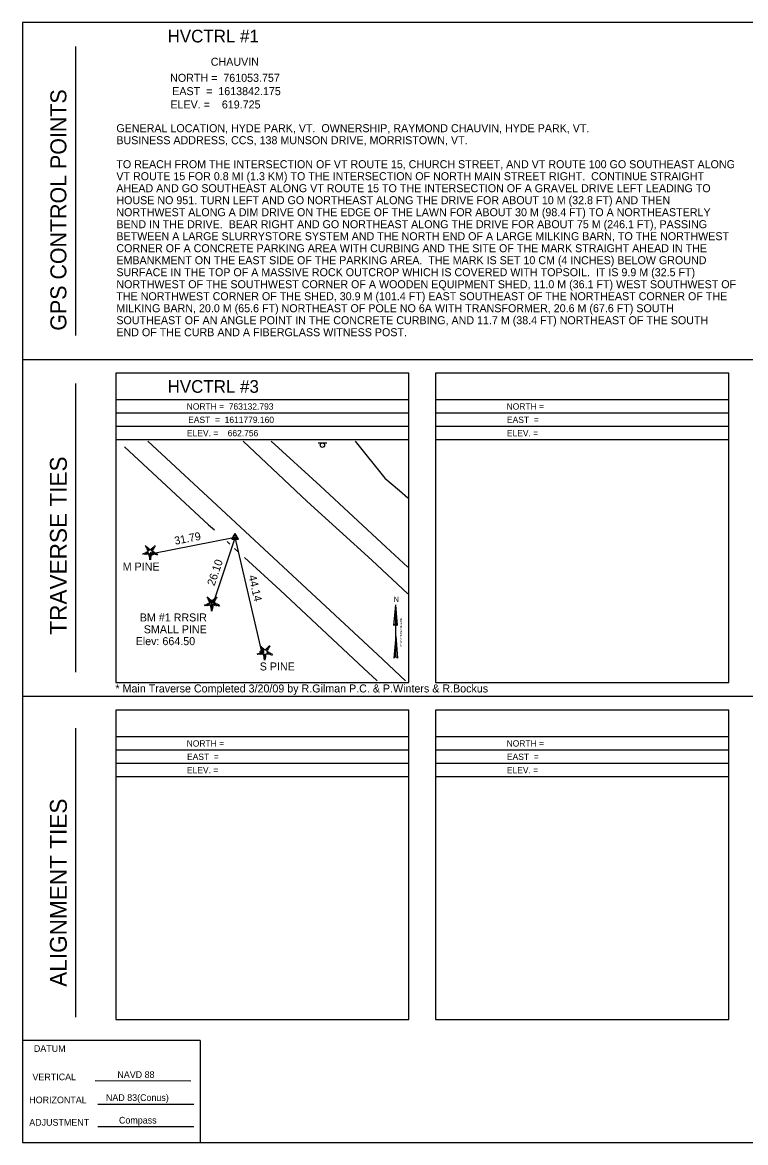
# Model space of a CAD drawing. Extents: x 1610875 to 1611515, y 762695 to 763115.
# Drawn here: x 1610874.6 to 1611145.9, y 762695 to 763115 of the extents above; entities that cross this region are included whole.
import ezdxf

# ---------------------------------------------------------------- set-up
doc = ezdxf.new("R2010")
doc.units = 0
for name, color, linetype in [('C_C', 7, 'Continuous'), ('CBP', 7, 'Continuous'), ('CPBM', 7, 'Continuous'), ('CPSM', 7, 'Continuous'), ('Default', 7, 'Continuous'), ('L_C', 7, 'Continuous'), ('LAWA', 7, 'Continuous'), ('LTC', 7, 'Continuous'), ('NBL2', 7, 'Continuous'), ('NNA_P', 7, 'Continuous'), ('PET', 7, 'Continuous'), ('PSP', 7, 'Continuous'), ('SSGN', 7, 'Continuous')]:
    doc.layers.add(name, color=color, linetype=linetype)

msp = doc.modelspace()

# ---------------------------------------------------------------- linework, layer by layer
at = {"layer": 'CBP'}
for centre, radius in [((1610923.26, 762915.95), 0.625), ((1610923.26, 762915.95), 0.0833), ((1610946.1, 762897.28), 0.625), ((1610946.1, 762897.28), 0.0833), ((1610964.42, 762878.99), 0.625), ((1610964.42, 762878.99), 0.0833)]:
    msp.add_circle(centre, radius, dxfattribs=at)
at = {"layer": 'CPBM'}
for p, q in [((1610945.07, 762897.36), (1610945.07, 762898.36)), ((1610945.07, 762898.36), (1610946.07, 762898.36)), ((1610946.07, 762897.36), (1610945.07, 762897.36)), ((1610945.58, 762897.87), (1610945.58, 762897.87)), ((1610945.58, 762897.87), (1610945.58, 762897.87)), ((1610946.07, 762898.36), (1610946.07, 762897.36))]:
    msp.add_line(p, q, dxfattribs=at)
at = {"layer": 'CPSM'}
for p, q in [((1610953.22, 762921.28), (1610954.47, 762923.44)), ((1610953.22, 762921.28), (1610954.47, 762922)), ((1610955.72, 762921.28), (1610954.47, 762923.44)), ((1610954.47, 762922), (1610954.47, 762923.44)), ((1610954.47, 762922), (1610954.47, 762922)), ((1610954.47, 762922), (1610955.72, 762921.28)), ((1610953.22, 762921.28), (1610955.72, 762921.28))]:
    msp.add_line(p, q, dxfattribs=at)
at = {"layer": 'Default'}
for p, q in [((1610923.26, 762915.95), (1610954.47, 762922)), ((1610954.47, 762922), (1610946.1, 762897.28)), ((1610964.42, 762878.99), (1610954.47, 762922))]:
    msp.add_line(p, q, dxfattribs=at)
at = {"layer": 'LAWA'}
msp.add_lwpolyline([(1610999.4, 762958.05), (1611010.54, 762944.1), (1611016.04, 762939.57), (1611019.14, 762936.77)], dxfattribs=at)
at = {"layer": 'LTC'}
for p, q in [((1610920.68, 762918.66), (1610921.03, 762918.92)), ((1610920.89, 762918.2), (1610921.42, 762918.58)), ((1610921.1, 762917.73), (1610921.8, 762918.24)), ((1610921.31, 762917.27), (1610922.18, 762917.91)), ((1610921.53, 762916.81), (1610922.54, 762917.55)), ((1610922.54, 762917.55), (1610923.54, 762916.82)), ((1610922.96, 762917.86), (1610923.77, 762917.27)), ((1610923.33, 762918.21), (1610924.01, 762917.71)), ((1610923.7, 762918.56), (1610924.25, 762918.16)), ((1610924.08, 762918.91), (1610924.49, 762918.6)), ((1610919.71, 762915.94), (1610919.86, 762915.48)), ((1610920.16, 762916.16), (1610920.38, 762915.51)), ((1610920.62, 762916.38), (1610920.89, 762915.54)), ((1610921.08, 762916.59), (1610921.41, 762915.57)), ((1610921.53, 762916.81), (1610921.92, 762915.62)), ((1610923.15, 762915.62), (1610921.92, 762915.62)), ((1610923.11, 762915.12), (1610921.96, 762915.12)), ((1610923.03, 762914.62), (1610922.04, 762914.62)), ((1610922.94, 762914.12), (1610922.11, 762914.12)), ((1610922.86, 762913.62), (1610922.18, 762913.62)), ((1610923.54, 762916.82), (1610923.15, 762915.62)), ((1610923.98, 762916.55), (1610923.64, 762915.51)), ((1610924.42, 762916.3), (1610924.13, 762915.42)), ((1610924.87, 762916.05), (1610924.63, 762915.32)), ((1610925.31, 762915.8), (1610925.12, 762915.23)), ((1610942.83, 762896.73), (1610942.98, 762896.26)), ((1610943.28, 762896.95), (1610943.49, 762896.3)), ((1610943.74, 762897.17), (1610944.01, 762896.33)), ((1610943.79, 762899.45), (1610944.15, 762899.71)), ((1610944, 762898.99), (1610944.53, 762899.37)), ((1610944.19, 762897.38), (1610944.52, 762896.36)), ((1610944.21, 762898.52), (1610944.92, 762899.03)), ((1610944.42, 762898.06), (1610945.3, 762898.69)), ((1610944.65, 762897.6), (1610945.66, 762898.34)), ((1610944.65, 762897.6), (1610945.03, 762896.41)), ((1610946.26, 762896.41), (1610945.03, 762896.41)), ((1610945.66, 762898.34), (1610946.65, 762897.61)), ((1610946.08, 762898.65), (1610946.89, 762898.06)), ((1610946.65, 762897.61), (1610946.26, 762896.41)), ((1610946.45, 762899), (1610947.13, 762898.5)), ((1610947.09, 762897.34), (1610946.75, 762896.3)), ((1610946.82, 762899.34), (1610947.37, 762898.95)), ((1610947.19, 762899.69), (1610947.61, 762899.39)), ((1610947.54, 762897.09), (1610947.25, 762896.2)), ((1610947.98, 762896.84), (1610947.74, 762896.11)), ((1610948.43, 762896.59), (1610948.24, 762896.01)), ((1610946.23, 762895.91), (1610945.08, 762895.91)), ((1610946.14, 762895.41), (1610945.15, 762895.41)), ((1610946.06, 762894.91), (1610945.23, 762894.91)), ((1610945.97, 762894.41), (1610945.3, 762894.41)), ((1610963.66, 762881.12), (1610964.02, 762881.38)), ((1610963.87, 762880.66), (1610964.4, 762881.04)), ((1610964.08, 762880.19), (1610964.79, 762880.7)), ((1610964.29, 762879.73), (1610965.17, 762880.36)), ((1610964.52, 762879.27), (1610965.53, 762880.01)), ((1610965.53, 762880.01), (1610966.53, 762879.28)), ((1610965.95, 762880.32), (1610966.76, 762879.73)), ((1610966.32, 762880.67), (1610967, 762880.17)), ((1610966.69, 762881.02), (1610967.24, 762880.62)), ((1610967.06, 762881.36), (1610967.48, 762881.06)), ((1610962.7, 762878.4), (1610962.85, 762877.94)), ((1610963.15, 762878.62), (1610963.36, 762877.97)), ((1610963.61, 762878.84), (1610963.88, 762878)), ((1610964.06, 762879.05), (1610964.39, 762878.03)), ((1610964.52, 762879.27), (1610964.9, 762878.08)), ((1610966.14, 762878.08), (1610964.9, 762878.08)), ((1610966.1, 762877.58), (1610964.95, 762877.58)), ((1610966.01, 762877.08), (1610965.02, 762877.08)), ((1610965.93, 762876.58), (1610965.1, 762876.58)), ((1610965.85, 762876.08), (1610965.17, 762876.08)), ((1610966.53, 762879.28), (1610966.14, 762878.08)), ((1610966.96, 762879.01), (1610966.63, 762877.97)), ((1610967.41, 762878.76), (1610967.12, 762877.88)), ((1610967.85, 762878.51), (1610967.62, 762877.78)), ((1610968.3, 762878.26), (1610968.11, 762877.69))]:
    msp.add_line(p, q, dxfattribs=at)
at = {"layer": 'NBL2'}
for p, q in [((1610894.6, 762997.69), (1610894.6, 763106.03)), ((1610874.6, 762988.69), (1611514.6, 762988.69)), ((1610894.6, 762871.36), (1610894.6, 762979.69)), ((1611019.6, 762973.53), (1610909.6, 762973.53)), ((1611139.6, 762973.53), (1611029.6, 762973.53)), ((1611019.6, 762968.53), (1610909.6, 762968.53)), ((1611139.6, 762968.53), (1611029.6, 762968.53)), ((1611019.6, 762963.53), (1610909.6, 762963.53)), ((1611139.6, 762963.53), (1611029.6, 762963.53)), ((1611019.6, 762958.53), (1610909.6, 762958.53)), ((1611139.6, 762958.53), (1611029.6, 762958.53)), ((1610874.6, 762862.36), (1611514.6, 762862.36)), ((1610894.6, 762742.03), (1610894.6, 762850.36)), ((1611019.6, 762847.19), (1610909.6, 762847.19)), ((1611139.6, 762847.19), (1611029.6, 762847.19)), ((1611019.6, 762842.19), (1610909.6, 762842.19)), ((1611139.6, 762842.19), (1611029.6, 762842.19)), ((1611019.6, 762837.19), (1610909.6, 762837.19)), ((1611139.6, 762837.19), (1611029.6, 762837.19)), ((1611019.6, 762832.19), (1610909.6, 762832.19)), ((1611139.6, 762832.19), (1611029.6, 762832.19)), ((1610941.27, 762733.28), (1610874.6, 762733.28)), ((1610941.27, 762733.28), (1610941.27, 762695.03)), ((1610941.27, 762733.28), (1610941.27, 762695.03)), ((1610901.84, 762718.26), (1610937.84, 762718.22)), ((1610902.95, 762709.48), (1610938.95, 762709.48)), ((1610902.95, 762701.05), (1610938.95, 762701.01))]:
    msp.add_line(p, q, dxfattribs=at)
for points in [[(1610874.6, 762695.03), (1611514.6, 762695.03), (1611514.6, 763115.03), (1610874.6, 763115.03)], [(1610909.6, 762867.53), (1611019.6, 762867.53), (1611019.6, 762983.53), (1610909.6, 762983.53)], [(1611029.6, 762867.53), (1611139.6, 762867.53), (1611139.6, 762983.53), (1611029.6, 762983.53)], [(1610909.6, 762741.19), (1611019.6, 762741.19), (1611019.6, 762857.19), (1610909.6, 762857.19)], [(1611029.6, 762741.19), (1611139.6, 762741.19), (1611139.6, 762857.19), (1611029.6, 762857.19)]]:
    msp.add_lwpolyline(points, close=True, dxfattribs=at)
at = {"layer": 'NNA_P'}
for p, q in [((1611013.95, 762888.92), (1611014.64, 762896.71)), ((1611014.64, 762877.33), (1611014.64, 762896.71)), ((1611015.33, 762888.92), (1611014.64, 762896.71)), ((1611013.95, 762888.92), (1611014.64, 762889.68)), ((1611015.34, 762888.92), (1611014.64, 762889.68)), ((1611014.64, 762884.86), (1611013.92, 762876.69)), ((1611014.64, 762884.86), (1611015.36, 762876.69)), ((1611014.64, 762877.33), (1611013.92, 762876.69)), ((1611014.64, 762877.33), (1611015.36, 762876.69))]:
    msp.add_line(p, q, dxfattribs=at)
at = {"layer": 'PET'}
for points in [[(1610921.61, 762958.05), (1610949.29, 762932.36), (1610975.88, 762907.65), (1611007.86, 762877.98), (1611018.32, 762868.21)], [(1611019.14, 762900.83), (1611005.68, 762913.39), (1610981.44, 762935.38), (1610957.39, 762958.05)]]:
    msp.add_lwpolyline(points, dxfattribs=at)
at = {"layer": 'PSP'}
for points in [[(1610912.94, 762955.88), (1610944.44, 762926.7), (1610946.6, 762924.74)], [(1611019.14, 762910.79), (1611011.01, 762918.3), (1610986.32, 762941.28), (1610967.87, 762958.05)], [(1610951.36, 762920.38), (1610952.39, 762919.44)], [(1610954.19, 762917.8), (1610955.47, 762916.63)], [(1610957.86, 762914.45), (1610971.27, 762902.2), (1611002.62, 762872.81), (1611007.63, 762868.21)]]:
    msp.add_lwpolyline(points, dxfattribs=at)
at = {"layer": 'SSGN'}
for p, q in [((1610985.5, 762957.36), (1610988.83, 762957.36)), ((1610987.14, 762956.53), (1610987.14, 762956.53))]:
    msp.add_line(p, q, dxfattribs=at)
msp.add_circle((1610987.14, 762956.53), 0.833, dxfattribs=at)

# ---------------------------------------------------------------- texts
at = {"layer": 'C_C'}
for s, p in [('BM #1 RRSIR', (1610918.64, 762890.42)), ('SMALL PINE', (1610920.14, 762885.98)), ('Elev: 664.50', (1610917.1, 762881.54))]:
    msp.add_text(s, height=3, dxfattribs=at).set_placement(p)
at = {"layer": 'Default'}
for s, p in [('GENERAL LOCATION, HYDE PARK, VT.  OWNERSHIP, RAYMOND CHAUVIN, HYDE PARK, VT. ', (1610909.85, 763073.86)), ('BUSINESS ADDRESS, CCS, 138 MUNSON DRIVE, MORRISTOWN, VT.', (1610909.85, 763069.36)), ('TO REACH FROM THE INTERSECTION OF VT ROUTE 15, CHURCH STREET, AND VT ROUTE 100 GO SOUTHEAST ALONG ', (1610909.85, 763060.36)), ('VT ROUTE 15 FOR 0.8 MI (1.3 KM) TO THE INTERSECTION OF NORTH MAIN STREET RIGHT.  CONTINUE STRAIGHT ', (1610909.85, 763055.86)), ('AHEAD AND GO SOUTHEAST ALONG VT ROUTE 15 TO THE INTERSECTION OF A GRAVEL DRIVE LEFT LEADING TO ', (1610909.85, 763051.36)), ('HOUSE NO 951. TURN LEFT AND GO NORTHEAST ALONG THE DRIVE FOR ABOUT 10 M (32.8 FT) AND THEN ', (1610909.85, 763046.86)), ('NORTHWEST ALONG A DIM DRIVE ON THE EDGE OF THE LAWN FOR ABOUT 30 M (98.4 FT) TO A NORTHEASTERLY ', (1610909.85, 763042.36)), ('BEND IN THE DRIVE.  BEAR RIGHT AND GO NORTHEAST ALONG THE DRIVE FOR ABOUT 75 M (246.1 FT), PASSING ', (1610909.85, 763037.86)), ('BETWEEN A LARGE SLURRYSTORE SYSTEM AND THE NORTH END OF A LARGE MILKING BARN, TO THE NORTHWEST ', (1610909.85, 763033.36)), ('CORNER OF A CONCRETE PARKING AREA WITH CURBING AND THE SITE OF THE MARK STRAIGHT AHEAD IN THE ', (1610909.85, 763028.86)), ('EMBANKMENT ON THE EAST SIDE OF THE PARKING AREA.  THE MARK IS SET 10 CM (4 INCHES) BELOW GROUND ', (1610909.85, 763024.36)), ('SURFACE IN THE TOP OF A MASSIVE ROCK OUTCROP WHICH IS COVERED WITH TOPSOIL.  IT IS 9.9 M (32.5 FT) ', (1610909.85, 763019.86)), ('NORTHWEST OF THE SOUTHWEST CORNER OF A WOODEN EQUIPMENT SHED, 11.0 M (36.1 FT) WEST SOUTHWEST OF ', (1610909.85, 763015.36)), ('THE NORTHWEST CORNER OF THE SHED, 30.9 M (101.4 FT) EAST SOUTHEAST OF THE NORTHEAST CORNER OF THE ', (1610909.85, 763010.86)), ('MILKING BARN, 20.0 M (65.6 FT) NORTHEAST OF POLE NO 6A WITH TRANSFORMER, 20.6 M (67.6 FT) SOUTH ', (1610909.85, 763006.36)), ('SOUTHEAST OF AN ANGLE POINT IN THE CONCRETE CURBING, AND 11.7 M (38.4 FT) NORTHEAST OF THE SOUTH ', (1610909.85, 763001.86)), ('END OF THE CURB AND A FIBERGLASS WITNESS POST.', (1610909.85, 762997.36)), ('* Main Traverse Completed 3/20/09 by R.Gilman P.C. & P.Winters & R.Bockus', (1610909.51, 762863.8))]:
    msp.add_text(s, height=3, dxfattribs=at).set_placement(p)
for s, rotation, p in [('31.79', 10.9672, (1610931.9, 762919.15)), ('26.10', 71.2964, (1610946.64, 762903.56)), ('44.14', 283.0245, (1610959.37, 762907.45))]:
    msp.add_text(s, height=3, rotation=rotation, dxfattribs=at).set_placement(p)
at = {"layer": 'L_C'}
for s, p in [('M PINE', (1610912.23, 762909.5)), ('S PINE', (1610963.64, 762872.05))]:
    msp.add_text(s, height=3, dxfattribs=at).set_placement(p)
at = {"layer": 'LTC'}
for p in [(1610922.42, 762916.56), (1610945.54, 762897.35), (1610965.41, 762879.02)]:
    msp.add_text('.', height=1.04, rotation=270, dxfattribs=at).set_placement(p)
at = {"layer": 'NBL2'}
for s, height, p in [('     HVCTRL #1     ', 4.75, (1610920.25, 763107.52)), ('   CHAUVIN  ', 3, (1610941.93, 763098.77)), ('NORTH =  761053.757 ', 3, (1610930.02, 763092.75)), ('EAST  =  1613842.175', 3, (1610930.81, 763087.75)), ('ELEV. =    619.725  ', 3, (1610930.13, 763082.75)), ('     HVCTRL #3     ', 4.75, (1610920.25, 762976.15)), ('NORTH =  763132.793 ', 2.375, (1610936.22, 762969.84)), ('NORTH =             ', 2.375, (1611056.22, 762969.84)), ('EAST  =  1611779.160', 2.375, (1610936.78, 762964.84)), ('EAST  =             ', 2.375, (1611056.36, 762964.84)), ('ELEV. =    662.756  ', 2.375, (1610936.33, 762959.84)), ('ELEV. =             ', 2.375, (1611056.33, 762959.84)), ('NORTH =             ', 2.375, (1610936.22, 762843.5)), ('NORTH =             ', 2.375, (1611056.22, 762843.5)), ('EAST  =             ', 2.375, (1610936.36, 762838.5)), ('EAST  =             ', 2.375, (1611056.36, 762838.5)), ('ELEV. =             ', 2.375, (1610936.33, 762833.5)), ('ELEV. =             ', 2.375, (1611056.33, 762833.5)), ('DATUM', 2.5, (1610878.92, 762729.04)), ('  NAVD 88 ', 2.5, (1610908.37, 762719.27)), ('HORIZONTAL', 2.5, (1610877.18, 762709.78)), ('NAD 83(Conus)', 2.5, (1610905.93, 762710.65)), ('ADJUSTMENT', 2.5, (1610877.18, 762701.34)), ('  Compass ', 2.5, (1610908.97, 762702.17))]:
    msp.add_text(s, height=height, dxfattribs=at).set_placement(p)
for s, height, rotation, p in [('GPS CONTROL POINTS', 6, 90, (1610891.1, 762999.44)), ('TRAVERSE TIES', 6.3332, 90, (1610891.27, 762885.46)), ('ALIGNMENT TIES', 6.3332, 90, (1610891.27, 762753.43)), ('VERTICAL', 2.5, 0.1439, (1610878.38, 762718.37))]:
    msp.add_text(s, height=height, rotation=rotation, dxfattribs=at).set_placement(p)
at = {"layer": 'NNA_P'}
msp.add_text('N', height=1.97, dxfattribs=at).set_placement((1611013.88, 762897.72))
msp.add_text('VT STATE PLANE GRID', height=0.7, rotation=90.0204, dxfattribs=at).set_placement((1611016.99, 762880.9))

doc.saveas('drawing.dxf')
